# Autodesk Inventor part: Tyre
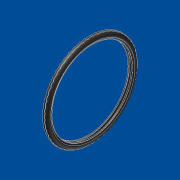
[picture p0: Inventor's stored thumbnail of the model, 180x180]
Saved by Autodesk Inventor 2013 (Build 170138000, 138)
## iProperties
Shininess: 20.0
Length Units: 11269
Angle Units: 11279
Time Units: 11290
Mass Units: 11283
Length Display Precision: 3
Angle Display Precision: 2
Created: 2001-04
Part Number: Tyre
Material: Standard
Document SubType Name: Modellieren
Designer: dl
Density: 1 g/cm^3
Density: 0.0
Volumn: 0.0
Area: 0.0
PropertySet Name: Model Information
Control State: 0
Master: False
Checked Out: False
Author: dl
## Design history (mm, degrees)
body "Solid1"
revolve "Revolution1" stored, may be unused: angle "d13" = 90 deg
workaxis "Work Axis1"
workplane "Work Plane1"
sketch "Sketch2"
  geometry: L1 (-12.3, 440.621)-(-12.3, 430.47) reference; A1 r 15.552 centre (-12.3, 433.368) between (2.314, 428.049) and (-26.914, 428.049) reference; A2 r 13.702 centre (-12.3, 433.368) between (0.576, 428.681) and (-25.176, 428.681) reference
workaxis "Work Axis2"
workplane "Work Plane2"
revolve "Revolution2" stored, may be unused: angle "d35" = 90 deg
workplane "Work Plane3"
sketch "Sketch6"
  geometry: L1 (24.092, 0)-(92.065, 0) reference; L2 (50.5, -240.71)-(50.5, 240.71) reference; L3 (58.5, -23.216)-(58.5, 23.216); A1 r 30 centre (77.5, 0) between (58.5, 23.216) and (58.5, -23.216)
  constraints: 2 end point, 2 point on circle, 1 centre point, 1 point on line, 1 vertical
  dimensions: "d40" = 27 distance from line of A1.centre L2; "d41" = 60 diameter of A1; "d48" = 19 distance from line of A1.centre L3
extrude "Extrusion1" cut sketch "Sketch6" stored distance "d42" = 10; taper "d43" = 0 deg
pattern_circular "Circular Pattern1" dims angle "d47" = 360 deg
workplane "Work Plane4"
sketch "Sketch7"
  geometry: L1 (30.5, 23.216)-(30.5, -23.216); L2 (38.5, 238.032)-(38.5, -238.032) reference; L3 (6.644, 0)-(74.617, 0) reference; A1 r 30 centre (11.5, 0) between (30.5, -23.216) and (30.5, 23.216)
  constraints: 2 end point, 2 point on circle, 1 centre point, 1 vertical
  dimensions: "d51" = 30 radius of A1; "d52" = 19 distance from line of A1.centre L1; "d54" = 27 distance from line of L2 A1.centre; "d55" = 0 distance from line of L3 A1.centre
extrude "Extrusion2" cut sketch "Sketch7" stored distance "d56" = 10; taper "d57" = 0 deg
pattern_circular "Circular Pattern2" dims angle "d60" = 360 deg
sketch "Sketch1"
  geometry: L1 (-49.669, 198.744)-(-49.669, 188.593); L2 (-61.969, -244.877)-(-61.969, 180.123) reference; L3 (-37.369, -241.877)-(-37.369, 177.123) reference; L4 (-51.41, 169.158)-(-47.928, 169.158) reference; L5 (-49.669, 169.158)-(-49.669, 172.009); L6 (-70.544, 174.998)-(-26.083, 174.998); L7 (-49.669, 191.491)-(-37.448, 191.491); L8 (-49.669, 191.491)-(-35.055, 186.172); L9 (-38.037, 176.981)-(-39.037, 178.713); L10 (-38.037, 176.981)-(-43.946, 175.939); L11 (-61.3, 176.981)-(-55.391, 175.939); L12 (-61.3, 176.981)-(-60.3, 178.713); L13 (-94.168, -32.194)-(8.417, -32.194); A1 r 13.702 centre (-49.669, 191.491) between (-36.793, 186.804) and (-62.545, 186.804); A2 r 1.3 centre (-37.369, 178.423) between (-38.669, 178.423) and (-37.369, 177.123) reference; A3 r 1.3 centre (-61.969, 178.423) between (-61.969, 177.123) and (-60.669, 178.423) reference; A4 r 1.3 centre (-37.369, 178.823) between (-37.369, 180.123) and (-38.669, 178.823) reference; A5 r 15.552 centre (-49.669, 191.491) between (-35.055, 186.172) and (-64.283, 186.172); A6 r 30 centre (-63.245, 196.432) between (-39.037, 178.713) and (-35.055, 186.172); A7 r 28 centre (-63.245, 196.432) between (-45.758, 174.565) and (-45.229, 174.998); A8 r 28.15 centre (-63.245, 196.432) between (-43.946, 175.939) and (-36.793, 186.804); A9 r 28.15 centre (-36.092, 196.432) between (-62.545, 186.804) and (-55.391, 175.939); A10 r 30 centre (-36.092, 196.432) between (-64.283, 186.172) and (-60.3, 178.713)
  constraints: 20 end point, 14 point on circle, 7 centre point, 4 tangent, 2 concentric, 2 parallel, 2 perpendicular, 2 point on line, 2 symmetric about line, 1 midpoint, 1 vertical, 4 other
  dimensions: "d3" = 0 distance between parallel lines of L1 L5; "d4" = 0 distance from line of A5.centre L1; "d6" = 20 deg angle of L8 L7; "d8" = 30 radius of A6; "d9" = 2 distance of L9.start L9.end; "d10" = 150 deg angle of L9 L1; "d11" = 70 deg angle of L10 L9; "d12" = 6 distance of L9.start L10.end
sketch "Sketch3"
  geometry: L1 (-18.3, 447.716)-(-18.3, 450.394); L2 (-6.3, 450.394)-(-6.3, 447.716); L3 (-35.189, 209.684)-(13.736, 209.684) reference; A1 r 15.552 centre (-12.3, 433.368) between (-6.3, 447.716) and (-27.852, 433.368); A2 r 18.052 centre (-12.3, 433.368) between (-6.3, 450.394) and (-18.3, 450.394)
  constraints: 5 point on circle, 4 end point, 2 centre point, 2 vertical
  dimensions: "d32" = 2.5 radial gap between concentric circles of A1 A2; "d33" = 6 horizontal distance of A1.centre L1.end; "d34" = 12 distance between parallel lines of L1 L2 (= 2 x d33)
sketch "Sketch4"
  geometry: L1 (-30.962, 209.684)-(12.583, 209.684) reference; A1 r 18.052 centre (-12.3, 433.368) between (3.252, 442.534) and (-27.852, 442.534)
  constraints: 2 point on circle, 1 centre point
body "Srf1"
sketch "Sketch5"
  geometry: L1 (-1.669, 420.59)-(-0.669, 418.858) reference; L2 (-0.669, 418.858)-(-6.577, 417.816) reference; L3 (-6.577, 1.551)-(-0.669, 0.509) reference; L4 (-0.669, 0.509)-(-1.669, -1.223) reference; L5 (-6.3, -28.349)-(-6.3, -31.026) reference; L6 (-18.3, -31.026)-(-18.3, -28.349) reference; L7 (-22.931, -1.223)-(-23.931, 0.509) reference; L8 (-23.931, 0.509)-(-18.023, 1.551) reference; L9 (-34.563, 209.684)-(17.384, 209.684) reference; L10 (3.252, -14.001)-(3.252, 209.684); A1 r 28.15 centre (1.277, 438.309) between (-25.176, 428.681) and (-18.023, 417.816) reference; A2 r 30 centre (-25.877, 438.309) between (-1.669, 420.59) and (2.314, 428.049) reference; A3 r 28.15 centre (-25.877, 438.309) between (-6.577, 417.816) and (0.576, 428.681) reference; A4 r 13.702 centre (-12.3, 433.368) between (0.576, 428.681) and (-25.176, 428.681) reference; A5 r 28.15 centre (1.277, -18.942) between (-18.023, 1.551) and (-25.176, -9.314) reference; A6 r 13.702 centre (-12.3, -14.001) between (-25.176, -9.314) and (0.576, -9.314) reference; A7 r 28.15 centre (-25.877, -18.942) between (0.576, -9.314) and (-6.577, 1.551) reference; A8 r 30 centre (-25.877, -18.942) between (2.314, -8.682) and (-1.669, -1.223) reference; A9 r 15.552 centre (-12.3, -14.001) between (-6.3, -28.349) and (2.314, -8.682) reference; A10 r 18.052 centre (-12.3, -14.001) between (-18.3, -31.026) and (-6.3, -31.026) reference; A11 r 15.552 centre (-12.3, -14.001) between (-26.914, -8.682) and (-18.3, -28.349) reference; A12 r 30 centre (1.277, -18.942) between (-22.931, -1.223) and (-26.914, -8.682) reference; A13 r 15.552 centre (-12.3, 433.368) between (3.252, 433.368) and (-27.852, 433.368); A14 r 15.552 centre (-12.3, 433.368) between (-19.963, 419.835) and (-19.963, 419.835)
  constraints: 6 point on circle, 2 centre point, 2 end point, 1 point on line
body "Srf2"
revolve "Revolution3" dims angle "d36" = 30 deg
revolve "Revolution4" dims angle "d37" = 30 deg
other parameters: "d0" = 2, "d1" = 18, "d5" = 2, "d7" = 2 (= d5), "d14" = 0, "d16" = 90 deg, "d19" = 0, "d21" = 0, "d23" = 90 deg, "d26" = 90 deg, "d28" = 90 deg, "d30" = 90 deg, "d31" = 90 deg, "d38" = 90 deg, "d39" = 90 deg, "d49" = 0.561, "d50" = 0.561
